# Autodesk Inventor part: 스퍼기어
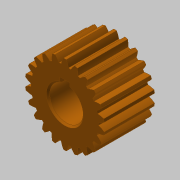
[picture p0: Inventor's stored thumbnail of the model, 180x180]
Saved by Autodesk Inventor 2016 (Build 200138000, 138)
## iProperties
Created: 2019-03
Part Number: 스퍼기어
Material: 강철
Document SubType Name: Modeling
Designer: mduedu
Categories: <?xml version="1.0" encoding="UTF-16"?> <MemberInstance><Categories><FamilyTemplate><FamilyTemplateParameter ValueType="xs:double" Id="1" ObjectReferenceKey="da
Density: 1 g/cm^3
Appearance: 주황색
CustomPartVersion: 1
Author: mduedu
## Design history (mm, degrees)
sketch "Sketch1"
  geometry: C1 r 23.6 at (0, 0)
  constraints: 1 centre point
  dimensions: "d0" = 47.2 diameter of C1 (= da_da)
extrude "Extrusion1" new body sketch "Sketch1" distance "d1" = 30 (= da_b); taper "d2" = 0 deg
workplane "Work Plane2"
sketch "Sketch2"
  geometry: C1 r 23.6 at (0, 0) reference; C2 r 22 at (0, 0)
  constraints: 1 centre point, 1 coincident
  dimensions: "d3" = 44 diameter of C2 (= da_dw)
feature "피치 지름" sketch "Sketch2" dims "d4" = 10, "d5" = 0
workplane "Work Plane8"
workplane "Work Plane9"
feature "스퍼 기어" dims "da_b" = 30, "da_d" = 44, "da_aw" = 44, "da_da" = 47.2, "da_df" = 40.172, "da_dw" = 44, angle "da_beta" = 0 deg, "da_lefttooth" = 0, "da_righttooth" = 0
sketch "스케치3"
  geometry: L1 (-3, 9.539)-(3, 9.539); L2 (3, 9.539)-(3, 12.8); L3 (3, 12.8)-(-3, 12.8); L4 (-3, 12.8)-(-3, 9.539); A1 r 10 centre (0, 0) between (-3, 9.539) and (3, 9.539); 1 further point
  constraints: 8 end point, 2 parallel, 2 point on circle, 1 centre point, 1 coincident, 1 horizontal, 1 perpendicular
  dimensions: "d49" = 20 diameter of A1; "d50" = 6 distance of L2.end L3.end; "d51" = 22.8 dimension on A1 L3
extrude "돌출2" cut sketch "스케치3" stored distance "d52" = 10; taper "d53" = 0 deg
chamfer "모따기1" distance "d54" = 1; stored, may be unused: second distance "d55" = 2, angle "d56" = 45 deg
body "Solid1"
body "Srf1"
other parameters: "d16" = 44 (= da_aw), "d17" = 0, "d34" = 1.428 (computed from da_z), "d39" = 0, "d41" = 0, "d43" = 44 (= da_aw), "d46" = 44 (= da_aw), "d47" = 0, "d48" = 0
